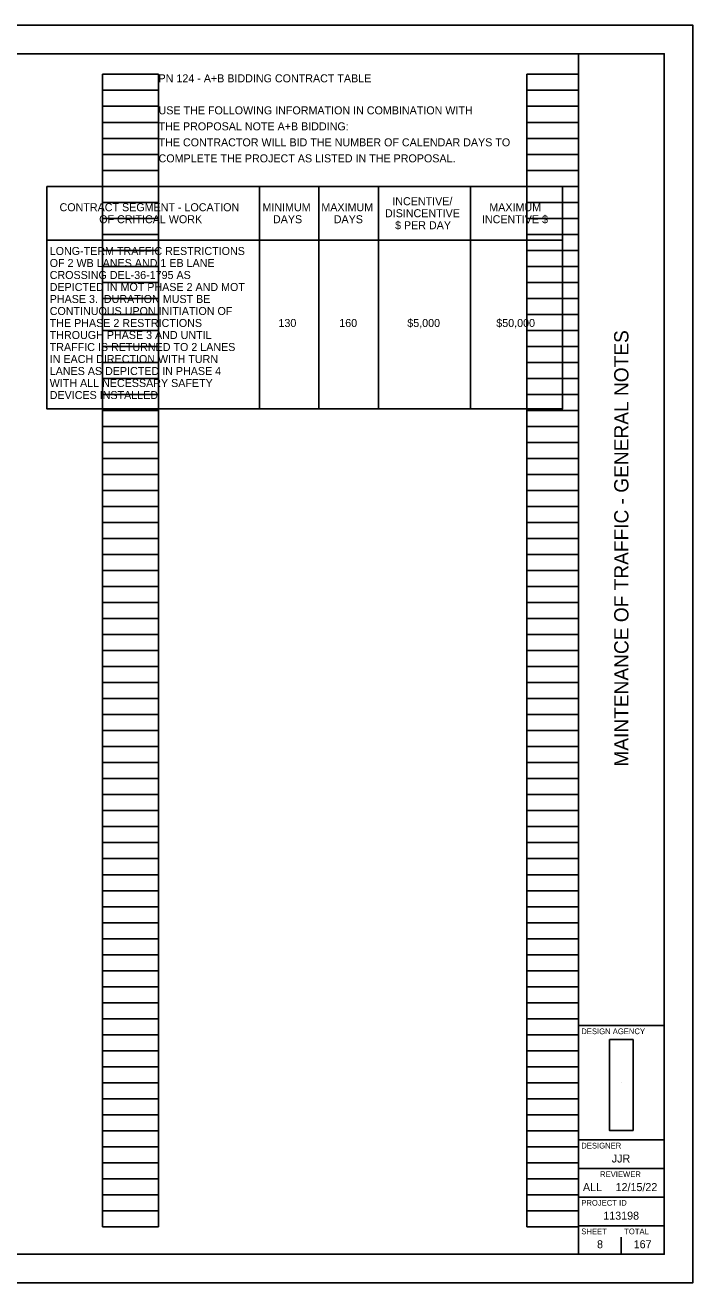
# Model space of a CAD drawing. Extents: x 0 to 34, y 0 to 22.
# Drawn here: x 22.33 to 34, y 0 to 22 of the extents above; entities that cross this region are included whole.
import ezdxf

# ---------------------------------------------------------------- set-up
doc = ezdxf.new("R2010")
doc.units = 0
for name, color, linetype in [('Default', 7, 'Continuous'), ('SH_Border', 7, 'Continuous'), ('SH_Cut_Line', 7, 'Continuous'), ('SH_Data', 7, 'Continuous'), ('SH_Text', 7, 'Continuous')]:
    doc.layers.add(name, color=color, linetype=linetype)

msp = doc.modelspace()

# ---------------------------------------------------------------- linework, layer by layer
at = {"layer": 'SH_Border'}
for p, q in [((32, 0.5), (32, 21.5)), ((32, 4.5), (33.5, 4.5)), ((32, 2.5), (33.5, 2.5)), ((32, 2), (33.5, 2)), ((32, 1.5), (33.5, 1.5)), ((32, 1), (33.5, 1))]:
    msp.add_line(p, q, dxfattribs=at)
msp.add_lwpolyline([(1.5, 21.5), (33.5, 21.5), (33.5, 0.5), (1.5, 0.5)], close=True, dxfattribs=at)
at = {"layer": 'SH_Cut_Line'}
msp.add_lwpolyline([(0, 0), (34, 0), (34, 22), (0, 22)], close=True, dxfattribs=at)
at = {"layer": 'SH_Data'}
for p, q in [((23.68, 0.98), (23.68, 21.14)), ((23.68, 21.14), (24.66, 21.14)), ((24.66, 0.98), (24.66, 21.14)), ((31.1, 0.98), (31.1, 21.14)), ((31.1, 21.14), (32, 21.14)), ((32, 0.98), (32, 21.14)), ((23.68, 20.86), (24.66, 20.86)), ((31.1, 20.86), (32, 20.86)), ((23.68, 20.58), (24.66, 20.58)), ((31.1, 20.58), (32, 20.58)), ((23.68, 20.3), (24.66, 20.3)), ((31.1, 20.3), (32, 20.3)), ((23.68, 20.02), (24.66, 20.02)), ((31.1, 20.02), (32, 20.02)), ((23.68, 19.74), (24.66, 19.74)), ((31.1, 19.74), (32, 19.74)), ((23.68, 19.46), (24.66, 19.46)), ((31.1, 19.46), (32, 19.46)), ((23.68, 19.18), (24.66, 19.18)), ((31.1, 19.18), (32, 19.18)), ((23.68, 18.9), (24.66, 18.9)), ((31.1, 18.9), (32, 18.9)), ((23.68, 18.62), (24.66, 18.62)), ((31.1, 18.62), (32, 18.62)), ((23.68, 18.34), (24.66, 18.34)), ((31.1, 18.34), (32, 18.34)), ((23.68, 18.06), (24.66, 18.06)), ((31.1, 18.06), (32, 18.06)), ((23.68, 17.78), (24.66, 17.78)), ((31.1, 17.78), (32, 17.78)), ((23.68, 17.5), (24.66, 17.5)), ((31.1, 17.5), (32, 17.5)), ((23.68, 17.22), (24.66, 17.22)), ((31.1, 17.22), (32, 17.22)), ((23.68, 16.94), (24.66, 16.94)), ((31.1, 16.94), (32, 16.94)), ((23.68, 16.66), (24.66, 16.66)), ((31.1, 16.66), (32, 16.66)), ((23.68, 16.38), (24.66, 16.38)), ((31.1, 16.38), (32, 16.38)), ((23.68, 16.1), (24.66, 16.1)), ((31.1, 16.1), (32, 16.1)), ((23.68, 15.82), (24.66, 15.82)), ((31.1, 15.82), (32, 15.82)), ((23.68, 15.54), (24.66, 15.54)), ((31.1, 15.54), (32, 15.54)), ((23.68, 15.26), (24.66, 15.26)), ((31.1, 15.26), (32, 15.26)), ((23.68, 14.98), (24.66, 14.98)), ((31.1, 14.98), (32, 14.98)), ((23.68, 14.7), (24.66, 14.7)), ((31.1, 14.7), (32, 14.7)), ((23.68, 14.42), (24.66, 14.42)), ((31.1, 14.42), (32, 14.42)), ((23.68, 14.14), (24.66, 14.14)), ((31.1, 14.14), (32, 14.14)), ((23.68, 13.86), (24.66, 13.86)), ((31.1, 13.86), (32, 13.86)), ((23.68, 13.58), (24.66, 13.58)), ((31.1, 13.58), (32, 13.58)), ((23.68, 13.3), (24.66, 13.3)), ((31.1, 13.3), (32, 13.3)), ((23.68, 13.02), (24.66, 13.02)), ((31.1, 13.02), (32, 13.02)), ((23.68, 12.74), (24.66, 12.74)), ((31.1, 12.74), (32, 12.74)), ((23.68, 12.46), (24.66, 12.46)), ((31.1, 12.46), (32, 12.46)), ((23.68, 12.18), (24.66, 12.18)), ((31.1, 12.18), (32, 12.18)), ((23.68, 11.9), (24.66, 11.9)), ((31.1, 11.9), (32, 11.9)), ((23.68, 11.62), (24.66, 11.62)), ((31.1, 11.62), (32, 11.62)), ((23.68, 11.34), (24.66, 11.34)), ((31.1, 11.34), (32, 11.34)), ((23.68, 11.06), (24.66, 11.06)), ((31.1, 11.06), (32, 11.06)), ((23.68, 10.78), (24.66, 10.78)), ((31.1, 10.78), (32, 10.78)), ((23.68, 10.5), (24.66, 10.5)), ((31.1, 10.5), (32, 10.5)), ((23.68, 10.22), (24.66, 10.22)), ((31.1, 10.22), (32, 10.22)), ((23.68, 9.94), (24.66, 9.94)), ((31.1, 9.94), (32, 9.94)), ((23.68, 9.66), (24.66, 9.66)), ((31.1, 9.66), (32, 9.66)), ((23.68, 9.38), (24.66, 9.38)), ((31.1, 9.38), (32, 9.38)), ((23.68, 9.1), (24.66, 9.1)), ((31.1, 9.1), (32, 9.1)), ((23.68, 8.82), (24.66, 8.82)), ((31.1, 8.82), (32, 8.82)), ((23.68, 8.54), (24.66, 8.54)), ((31.1, 8.54), (32, 8.54)), ((23.68, 8.26), (24.66, 8.26)), ((31.1, 8.26), (32, 8.26)), ((23.68, 7.98), (24.66, 7.98)), ((31.1, 7.98), (32, 7.98)), ((23.68, 7.7), (24.66, 7.7)), ((31.1, 7.7), (32, 7.7)), ((23.68, 7.42), (24.66, 7.42)), ((31.1, 7.42), (32, 7.42)), ((23.68, 7.14), (24.66, 7.14)), ((31.1, 7.14), (32, 7.14)), ((23.68, 6.86), (24.66, 6.86)), ((31.1, 6.86), (32, 6.86)), ((23.68, 6.58), (24.66, 6.58)), ((31.1, 6.58), (32, 6.58)), ((23.68, 6.3), (24.66, 6.3)), ((31.1, 6.3), (32, 6.3)), ((23.68, 6.02), (24.66, 6.02)), ((31.1, 6.02), (32, 6.02)), ((23.68, 5.74), (24.66, 5.74)), ((31.1, 5.74), (32, 5.74)), ((23.68, 5.46), (24.66, 5.46)), ((31.1, 5.46), (32, 5.46)), ((23.68, 5.18), (24.66, 5.18)), ((31.1, 5.18), (32, 5.18)), ((23.68, 4.9), (24.66, 4.9)), ((31.1, 4.9), (32, 4.9)), ((23.68, 4.62), (24.66, 4.62)), ((31.1, 4.62), (32, 4.62)), ((23.68, 4.34), (24.66, 4.34)), ((31.1, 4.34), (32, 4.34)), ((23.68, 4.06), (24.66, 4.06)), ((31.1, 4.06), (32, 4.06)), ((23.68, 3.78), (24.66, 3.78)), ((31.1, 3.78), (32, 3.78)), ((23.68, 3.5), (24.66, 3.5)), ((31.1, 3.5), (32, 3.5)), ((32.75, 3.5), (32.75, 3.5)), ((23.68, 3.22), (24.66, 3.22)), ((31.1, 3.22), (32, 3.22)), ((23.68, 2.94), (24.66, 2.94)), ((31.1, 2.94), (32, 2.94)), ((23.68, 2.66), (24.66, 2.66)), ((31.1, 2.66), (32, 2.66)), ((23.68, 2.38), (24.66, 2.38)), ((31.1, 2.38), (32, 2.38)), ((23.68, 2.1), (24.66, 2.1)), ((31.1, 2.1), (32, 2.1)), ((23.68, 1.82), (24.66, 1.82)), ((31.1, 1.82), (32, 1.82)), ((23.68, 1.54), (24.66, 1.54)), ((31.1, 1.54), (32, 1.54)), ((23.68, 1.26), (24.66, 1.26)), ((31.1, 1.26), (32, 1.26)), ((23.68, 0.98), (24.66, 0.98)), ((31.1, 0.98), (32, 0.98)), ((32.375, 0.675), (32.375, 0.675)), ((32.75, 0.5), (32.75, 0.8))]:
    msp.add_line(p, q, dxfattribs=at)
at = {"layer": 'SH_Text'}
for p, q in [((26.424, 19.18), (26.424, 15.288)), ((27.463, 19.18), (27.463, 15.288)), ((28.502, 19.18), (28.502, 15.288)), ((30.113, 19.18), (30.113, 15.288)), ((31.723, 19.18), (31.723, 17.301)), ((22.709, 18.24), (31.723, 18.24))]:
    msp.add_line(p, q, dxfattribs=at)
for points in [[(22.709, 19.18), (31.723, 19.18), (31.723, 15.288), (22.709, 15.288)], [(32.956, 2.664), (32.956, 4.254), (32.544, 4.254), (32.544, 2.664)]]:
    msp.add_lwpolyline(points, close=True, dxfattribs=at)

# ---------------------------------------------------------------- texts
at = {"layer": 'Default'}
for s, p in [('PN 124 - A+B BIDDING CONTRACT TABLE', (24.66, 21)), ('USE THE FOLLOWING INFORMATION IN COMBINATION WITH', (24.66, 20.44)), ('THE PROPOSAL NOTE A+B BIDDING:', (24.66, 20.16)), ('THE CONTRACTOR WILL BID THE NUMBER OF CALENDAR DAYS TO', (24.66, 19.88)), ('COMPLETE THE PROJECT AS LISTED IN THE PROPOSAL.', (24.66, 19.6))]:
    msp.add_text(s, height=0.14, dxfattribs=at).set_placement(p)
at = {"layer": 'SH_Data'}
msp.add_text('MAINTENANCE OF TRAFFIC - GENERAL NOTES', height=0.25, rotation=90, dxfattribs=at).set_placement((32.875, 9.03))
for s, height, p in [('DESIGN AGENCY', 0.1, (32.05, 4.35)), ('DESIGNER', 0.1, (32.05, 2.35)), ('JJR', 0.14, (32.583, 2.105)), ('REVIEWER', 0.1, (32.378, 1.85)), ('ALL', 0.14, (32.079, 1.605)), ('12/15/22', 0.14, (32.65, 1.605)), ('PROJECT ID', 0.1, (32.05, 1.35)), ('113198', 0.14, (32.435, 1.105)), ('SHEET', 0.1, (32.05, 0.85)), ('TOTAL', 0.1, (32.8, 0.85)), ('8', 0.14, (32.325, 0.605)), ('167', 0.14, (32.966, 0.605))]:
    msp.add_text(s, height=height, dxfattribs=at).set_placement(p)
at = {"layer": 'SH_Text'}
for s, p in [('INCENTIVE/', (28.746, 18.85)), ('CONTRACT SEGMENT - LOCATION', (22.929, 18.745)), ('MINIMUM ', (26.476, 18.745)), ('MAXIMUM', (27.506, 18.745)), ('DISINCENTIVE', (28.618, 18.64)), ('MAXIMUM ', (30.442, 18.745)), ('OF CRITICAL WORK', (23.622, 18.535)), ('DAYS', (26.66, 18.535)), ('DAYS', (27.723, 18.535)), ('$ PER DAY', (28.794, 18.43)), ('INCENTIVE $', (30.313, 18.535)), ('LONG-TERM TRAFFIC RESTRICTIONS ', (22.757, 17.98)), ('OF 2 WB LANES AND 1 EB LANE ', (22.757, 17.77)), ('CROSSING DEL-36-1795 AS', (22.757, 17.56)), ('DEPICTED IN MOT PHASE 2 AND MOT', (22.757, 17.35)), ('PHASE 3.\xa0 DURATION MUST BE', (22.757, 17.14)), ('CONTINUOUS UPON INITIATION OF', (22.757, 16.93)), ('THE PHASE 2 RESTRICTIONS', (22.757, 16.72)), ('130', (26.756, 16.72)), ('160', (27.819, 16.72)), ('$5,000', (29.008, 16.72)), ('$50,000', (30.564, 16.72)), ('THROUGH PHASE 3 AND UNTIL', (22.757, 16.51)), ('TRAFFIC IS RETURNED TO 2 LANES', (22.757, 16.3)), ('IN EACH DIRECTION WITH TURN', (22.757, 16.09)), ('LANES AS DEPICTED IN PHASE 4', (22.757, 15.88)), ('WITH ALL NECESSARY SAFETY', (22.757, 15.67)), ('DEVICES INSTALLED', (22.757, 15.46))]:
    msp.add_text(s, height=0.14, dxfattribs=at).set_placement(p)

doc.saveas('drawing.dxf')
